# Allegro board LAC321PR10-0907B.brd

Outline 256.5 x 150.9 mm; copper layers: TOP, IN1, GND1, IN2, GND2, GND3, IN3, GND4, VCC, BOTTOM. Coordinates in mm from the lower left corner of the outline.
Outline path: 0,37.6 arc(0.15,37.95) 0.5,38.1 6.6,38.1 arc(8.8,40.3) 6.6,42.5 4.25,42.5 arc(3.9,42.65) 3.75,43 3.75,58.19 arc(3.6,58.54) 3.25,58.69 3.18,58.69 arc(2.83,58.84) 2.68,59.19 2.68,59.55 arc(2.53,59.9) 2.18,60.05 1.8,60.05 arc(1.45,60.2) 1.3,60.55 1.3,99.71 arc(1.45,100.06) 1.8,100.21 2.1,100.21 arc(2.45,100.36) 2.6,100.71 2.6,111.4 arc(2.75,111.75) 3.1,111.9 12.4,111.9 arc(12.75,111.75) 12.9,111.4 12.9,107.08 arc(12.83,106.83) 12.65,106.64 arc(12.54,105.86) 13.33,105.96 arc(13.51,106.14) 13.76,106.21 33.33,106.21 arc(33.58,106.14) 33.76,105.96 arc(34.55,105.86) 34.45,106.64 arc(34.26,106.83) 34.2,107.08 34.2,111.4 arc(34.34,111.75) 34.7,111.9 38.55,111.9 arc(38.9,112.05) 39.05,112.4 39.05,150.4 arc(39.2,150.75) 39.55,150.9 80.12,150.9 arc(80.47,150.75) 80.62,150.4 80.62,139.9 arc(80.77,139.55) 81.12,139.4 131.84,139.4 arc(132.19,139.25) 132.34,138.9 132.34,134.15 arc(132.49,133.8) 132.84,133.65 139,133.65 arc(139.35,133.8) 139.5,134.15 139.5,138.9 arc(139.65,139.25) 140,139.4 185.62,139.4 arc(185.97,139.55) 186.12,139.9 186.12,150.4 arc(186.27,150.75) 186.62,150.9 246,150.9 arc(246.35,150.75) 246.5,150.4 246.5,145.9 arc(246.65,145.55) 247,145.4 256,145.4 arc(256.35,145.25) 256.5,144.9 256.5,130.12 arc(256.35,129.77) 256,129.62 255.44,129.62 arc(255.09,129.48) 254.94,129.12 254.94,128.77 arc(254.79,128.42) 254.44,128.27 251.11,128.27 arc(250.86,128.34) 250.67,128.52 arc(249.89,128.63) 249.99,127.84 arc(250.17,127.66) 250.24,127.41 250.24,107.84 arc(250.17,107.59) 249.99,107.41 arc(249.89,106.62) 250.67,106.72 arc(250.86,106.91) 251.11,106.97 254.44,106.97 arc(254.79,106.83) 254.94,106.47 254.94,105 arc(254.79,104.65) 254.44,104.5 208.54,104.5 arc(208.21,104.38) 208.04,104.06 arc(207.88,103.75) 207.55,103.63 204.05,103.63 arc(203.8,103.69) 203.61,103.88 arc(202.83,103.98) 202.93,103.19 arc(203.11,103.01) 203.18,102.76 203.18,83.19 arc(203.11,82.94) 202.93,82.76 arc(202.83,81.97) 203.61,82.08 arc(203.8,82.26) 204.05,82.33 207.54,82.33 arc(207.89,82.18) 208.04,81.83 208.04,80.33 arc(207.89,79.98) 207.54,79.83 173.54,79.83 arc(173.19,79.98) 173.04,80.33 173.04,82.33 arc(172.89,82.68) 172.54,82.83 160.96,82.83 arc(160.63,82.95) 160.46,83.25 arc(159.61,84.74) 158,85.33 153,85.33 arc(151.39,84.74) 150.54,83.25 arc(150.36,82.95) 150.04,82.83 144.75,82.83 arc(144.4,82.68) 144.25,82.33 144.25,78.83 arc(144.1,78.48) 143.75,78.33 142.16,78.33 arc(141.84,78.45) 141.67,78.75 arc(139.1,80.93) 136.53,78.75 arc(136.36,78.45) 136.04,78.33 45.06,78.33 arc(44.02,78.62) 43.29,79.4 42.75,80.07 arc(39.35,79.63) 40.18,76.29 arc(40.96,75.56) 41.25,74.52 41.25,0.5 arc(41.1,0.15) 40.75,0 7,0 arc(6.65,0.15) 6.5,0.5 6.5,3.85 arc(6.62,4.17) 6.91,4.34 arc(8.69,6.7) 6.5,8.7 0.5,8.7 arc(0.15,8.85) 0,9.2 0,11.53 arc(0.15,11.88) 0.5,12.03 5,12.03 arc(5.5,11.53) 6,12.03 6,20.98 arc(5.5,21.48) 5,20.98 1.5,20.98 arc(1.15,21.13) 1,21.48 1,25.53 arc(1.15,25.88) 1.5,26.03 5,26.03 arc(5.5,25.53) 6,26.03 6,34.98 arc(5.5,35.48) 5,34.98 0.5,34.98 arc(0.15,35.13) 0,35.48 0,37.6

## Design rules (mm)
net group 8: nets H_PROCHOT# H_PROCHOT#_R
net group CLK_CK-XDP: nets CK_XDP CK_XDP#
net group CLK_PCIE2: nets CLK_PCIE2#_R CLK_PCIE2_R
net group CLK_PCIE3: nets CLK_PCIE3 CLK_PCIE3#
net group CLK_PCIE4: nets CLK_PCIE4 CLK_PCIE4#
net group CSI_SKYCAM-CSI0: nets SKYCAM_CSI0_D#_L SKYCAM_CSI0_D_L
net group CSI_SKYCAM-CSI2: nets SKYCAM_CSI2_D#_L SKYCAM_CSI2_D_L
net group CSI_SKYCAM-CSI3: nets SKYCAM_CSI3_D#_L SKYCAM_CSI3_D_L
net group CSI_SKYCAM-CSI-CLK-L: nets SKYCAM_USER_CSI_CLK_D#_L SKYCAM_USER_CSI_CLK_D_L
net group CSI_SYCAM-CSI1: nets SKYCAM_CSI1_D#_L SKYCAM_CSI1_D_L
net group CSI_SYCAM-USER-CSI0: nets SKYCAM_USER_CSI0_D#_L SKYCAM_USER_CSI0_D_L
net group CSI_SYCAM-USER-CSI1: nets SKYCAM_USER_CSI1_D#_L SKYCAM_USER_CSI1_D_L
net group DDI_BASE_DDI_AUX_DEV_D: nets BASE_DDI_AUX_DEV_DN BASE_DDI_AUX_DEV_DP
net group DDI_BASE_DDI_LANE0_DEV_D: nets BASE_DDI_LANE0_DEV_DN BASE_DDI_LANE0_DEV_DP
net group DDI_BASE_DDI_LANE1_DEV_D: nets BASE_DDI_LANE1_DEV_DN BASE_DDI_LANE1_DEV_DP
net group DDI_BASE_DDI_LANE2_DEV_D: nets BASE_DDI_LANE2_DEV_DN BASE_DDI_LANE2_DEV_DP
net group DDI_BASE_DDI_LANE3_DEV_D: nets BASE_DDI_LANE3_DEV_DN BASE_DDI_LANE3_DEV_DP
net group DIFFPAIR32: nets TBTA_CA2HD_0_N TBTA_CA2HD_0_P
net group DIFFPAIR33: nets TBTA_CA2HD_1_N TBTA_CA2HD_1_P
net group DIFFPAIR34: nets TBTB_CA2HD_0_N TBTB_CA2HD_0_P
net group DIFFPAIR35: nets TBTB_HD2CA_0_N TBTB_HD2CA_0_P
net group DIFFPAIR36: nets TBTB_TX0_N TBTB_TX0_P
net group DIFFPAIR37: nets TBTB_HD2CA_1_N TBTB_HD2CA_1_P
net group DIFFPAIR38: nets TBTB_CA2HD_1_N TBTB_CA2HD_1_P
net group DIFFPAIR39: nets TBTB_TX1_N TBTB_TX1_P
net group DIFFPAIR40: nets TBT_SNK0_ML0_N_L TBT_SNK0_ML0_P_L
net group DIFFPAIR41: nets TBT_SNK0_ML1_N_L TBT_SNK0_ML1_P_L
net group DIFFPAIR42: nets TBT_SNK0_ML2_N_L TBT_SNK0_ML2_P_L
net group DIFFPAIR43: nets TBT_SNK0_ML3_N_L TBT_SNK0_ML3_P_L
net group DIFFPAIR44: nets TBT_SNK0_AUX_N TBT_SNK0_AUX_P
net group DIFFPAIR45: nets TBT_SNK0_AUX_N_L TBT_SNK0_AUX_P_L
net group DIFFPAIR46: nets TBTB_USB2_D_N TBTB_USB2_D_P
net group DIFFPAIR47: nets TBTA_USB2_D_N TBTA_USB2_D_P
net group DIFFPAIR48: nets TBTB_AUX_N TBTB_AUX_P
net group DIFFPAIR49: nets TBTB_DPSRC_AUX_N TBTB_DPSRC_AUX_P
net group DIFFPAIR50: nets PCH_DDI1_AUXN PCH_DDI1_AUXP
net group DIFFPAIR51: nets TBT_SNK0_ML0_N TBT_SNK0_ML0_P
net group DIFFPAIR52: nets TBT_SNK0_ML1_N TBT_SNK0_ML1_P
net group DIFFPAIR53: nets TBT_SNK0_ML2_N TBT_SNK0_ML2_P
net group DIFFPAIR54: nets TBT_SNK0_ML3_N TBT_SNK0_ML3_P
net group DIFFPAIR56: nets USB3RN2 USB3RP2
net group DIFFPAIR57: nets USB3TN4 USB3TP4
net group DIFFPAIR59: nets USB3RN3 USB3RP3
net group DIFFPAIR60: nets USB3TN2_RC_CON USB3TP2_RC_CON
net group DIFFPAIR61: nets USB3RN2_RC_CON USB3RP2_RC_CON
net group DIFFPAIR67: nets CLK_PCIE4#_R CLK_PCIE4_R
net group DIFFPAIR68: nets CLK_PCIE3#_R CLK_PCIE3_R
net group DIFFPAIR69: nets SKYCAM_USER_CSI_CLK_D SKYCAM_USER_CSI_CLK_D#
net group DIFFPAIR70: nets USB3TN4_R USB3TP4_R
net group DIFFPAIR81: nets CLK_XDP#_L CLK_XDP_L
net group DIFFPAIR92: nets REM_DIODE3_N REM_DIODE3_P
net group DIFFPAIR93: nets REM_DIODE1_N REM_DIODE1_P
net group DP1_USB3TN3_RC_CON: nets USB3TN3_RC_CON USB3TP3_RC_CON
net group DP-PCH_DDI1_AUX: nets PCH_DDI1_AUXN_R PCH_DDI1_AUXP_R
net group DP_BASE_DDI_AUX_DEV_DN_L: nets BASE_DDI_AUX_DEV_DN_L BASE_DDI_AUX_DEV_DP_L
net group DP_BASE_DDI_LANE0_DEV_DN_L: nets BASE_DDI_LANE0_DEV_DN_L BASE_DDI_LANE0_DEV_DP_L
net group DP_BASE_DDI_LANE1_DEV_DN_L: nets BASE_DDI_LANE1_DEV_DN_L BASE_DDI_LANE1_DEV_DP_L
net group DP_BASE_DDI_LANE2_DEV_DN_L: nets BASE_DDI_LANE2_DEV_DN_L BASE_DDI_LANE2_DEV_DP_L
net group DP_BASE_DDI_LANE3_DEV_DN_L: nets BASE_DDI_LANE3_DEV_DN_L BASE_DDI_LANE3_DEV_DP_L
net group DP_CLK_PCIE2: nets CLK_PCIE2 CLK_PCIE2#
net group DP_PCH_DDI1_N0_R: nets PCH_DDI1_N0 PCH_DDI1_P0
net group DP_PCH_DDI1_N1_R: nets PCH_DDI1_N1 PCH_DDI1_P1
net group DP_PCH_DDI1_N2_R: nets PCH_DDI1_N2 PCH_DDI1_P2
net group DP_PCH_DDI1_N3_R: nets PCH_DDI1_N3 PCH_DDI1_P3
net group DP_SKYCAM_CSI0_D: nets SKYCAM_CSI0_D SKYCAM_CSI0_D#
net group DP_SKYCAM_CSI1_D: nets SKYCAM_CSI1_D SKYCAM_CSI1_D#
net group DP_SKYCAM_CSI2_D: nets SKYCAM_CSI2_D SKYCAM_CSI2_D#
net group DP_SKYCAM_CSI3_D: nets SKYCAM_CSI3_D SKYCAM_CSI3_D#
net group DP_SKYCAM_USER_CSI0_D: nets SKYCAM_USER_CSI0_D SKYCAM_USER_CSI0_D#
net group DP_SKYCAM_USER_CSI1_D: nets SKYCAM_USER_CSI1_D SKYCAM_USER_CSI1_D#
net group DP_USB3RN1_RC_CON: nets USB3RN1_RC_CON USB3RP1_RC_CON
net group DP_USB3TN2: nets USB3TN2 USB3TP2
net group DP_USB3TN3_RC_CON: nets N55977579 N55977609
net group DP_USB20_N5_R: nets USB20_N5_R USB20_P5_R
net group EDP_AUX-CON: nets EDP_AUXN_CONN EDP_AUXP_CONN
net group EDP_TX-P0-CON: nets EDP_TXN_P0_CONN EDP_TXP_P0_CONN
net group EDP_TX-P1-CON: nets EDP_TXN_P1_CONN EDP_TXP_P1_CONN
net group EDP_TX-P2-CON: nets EDP_TXN_P2_CONN EDP_TXP_P2_CONN
net group EDP_TX-P3-CON: nets EDP_TXN_P3_CONN EDP_TXP_P3_CONN
net group HP2_D: nets HP2_D_L HP2_D_R
net group HP2_D-C: nets HP2_D_L_C HP2_D_R_C
net group HP2_D-R: nets HP2_D_L_R HP2_D_R_R
net group LINE: nets LINE_L LINE_R
net group LINE1: nets LINE1_L LINE1_R
net group LINE1-C: nets LINE1_L_C LINE1_R_C
net group PCIE_PRX-DRX5-C: nets PCIE_PTX_DRX_N5_C PCIE_PTX_DRX_P5_C
net group PCIE_PRX-DRX7: nets PCIE_PTX_DRX_N7 PCIE_PTX_DRX_P7
net group PCIE_PRX-DRX7-C: nets PCIE_PTX_DRX_N7_C PCIE_PTX_DRX_P7_C
net group PCIE_PRX-DRX8: nets PCIE_PTX_DRX_N8 PCIE_PTX_DRX_P8
net group PCIE_PRX-DRX8-C: nets PCIE_PTX_DRX_N8_C PCIE_PTX_DRX_P8_C
net group PCIE_PRX-DRX9: nets PCIE_PTX_DRX_N9 PCIE_PTX_DRX_P9
net group PCIE_PRX-DRX9-C: nets PCIE_PTX_DRX_N9_C PCIE_PTX_DRX_P9_C
net group PCIE_PRX-DTX7: nets PCIE_PRX_DTX_N7 PCIE_PRX_DTX_P7
net group PCIE_PRX-DTX8: nets PCIE_PRX_DTX_N8 PCIE_PRX_DTX_P8
net group PCIE_PRX-DTX9: nets PCIE_PRX_DTX_N9 PCIE_PRX_DTX_P9
net group PCIE_PRX_DTX_7_R: nets PCIE_PRX_DTX_N7_R PCIE_PRX_DTX_P7_R
net group REM_DIODE2_N: nets REM_DIODE2_N REM_DIODE2_P
net group TBTA_I2C_D_N: nets TBTA_I2C_D_N TBTA_I2C_D_N_R
net group TBTA_I2C_D_P: nets TBTA_I2C_D_P TBTA_I2C_D_P_R
net group TBTA_USB2_D_N_R: nets TBTA_USB2_D_N_R USBC1_USB2_D_N_R
net group TBTA_USB2_D_P_R: nets TBTA_USB2_D_P_R USBC1_USB2_D_P_R
net group TBTB_I2C_D_N: nets TBTB_I2C_D_N TBTB_I2C_D_N_R
net group TBTB_I2C_D_P: nets TBTB_I2C_D_P TBTB_I2C_D_P_R
net group TBTB_USB2_D_N_R: nets TBTB_USB2_D_N_R USBC2_USB2_D_N_R
net group TBTB_USB2_D_P_R: nets TBTB_USB2_D_P_R USBC2_USB2_D_P_R
net group USB3_R1: nets USB3RN1 USB3RP1
net group USB3_R3: nets USB3RN3_RC_CON USB3RP3_RC_CON
net group USB3_R4: nets USB3RN4 USB3RP4
net group USB3_T2: nets USB3TN2_R USB3TP2_R
net group USB3_T3: nets USB3TN3 USB3TP3
net group USB20_5: nets USB20_N5 USB20_P5
net group USB20_N9: nets USB20_N9 USB20_N9_R
net group USB20_P9: nets USB20_P9 USB20_P9_R
net group 5: nets LPC_AD0 LPC_AD1 LPC_AD2 LPC_AD3 LPC_FRAME#
net group 43H: nets MEC_XTAL1 MEC_XTAL2 PBTN_OUT#_R
net group 45H: nets OSC_IN OSC_OUT PCH_RTCX1 PCH_RTCX2 XTAL24_IN XTAL24_OUT
net group CLK: nets CLK_PCIE5 CLK_PCIE5#_R CLK_PCIE5_R TBT_REFCLK_100_N TBT_REFCLK_100_N_R TBT_REFCLK_100_P TBT_REFCLK_100_P_R
net group CLK_PCIE5: nets CLK_PCIE5#
net group CSI: nets SKYCAM_CSI_CLK_D# SKYCAM_CSI_CLK_D#_L SKYCAM_CSI_CLK_D_L
net group DDI1: nets PCH_DDI1_N0_R PCH_DDI1_N1_R PCH_DDI1_N2_R PCH_DDI1_N3_R PCH_DDI1_P0_R PCH_DDI1_P1_R PCH_DDI1_P2_R PCH_DDI1_P3_R
net group DDI2: nets DPSNK1_AUX_N DPSNK1_AUX_P DPSNK1_ML0_N DPSNK1_ML0_P DPSNK1_ML1_N DPSNK1_ML1_P DPSNK1_ML2_N DPSNK1_ML2_P DPSNK1_ML3_N DPSNK1_ML3_P TBT_SNK1_AUX_N TBT_SNK1_AUX_P TBT_SNK1_ML0_N TBT_SNK1_ML0_P TBT_SNK1_ML1_N TBT_SNK1_ML1_P TBT_SNK1_ML2_N TBT_SNK1_ML2_P TBT_SNK1_ML3_N TBT_SNK1_ML3_P
net group DDR3_CKE: nets M_A_CKE0 M_A_CKE1 M_A_CKE2 M_A_CKE3 M_B_CKE0 M_B_CKE1 M_B_CKE2 M_B_CKE3
net group DDR3_M-A-CA0: nets M_A_CA_0_0 M_A_CA_0_1 M_A_CA_0_2 M_A_CA_0_3 M_A_CA_0_4 M_A_CA_0_5 M_A_CA_0_6 M_A_CA_0_7 M_A_CA_0_8 M_A_CA_0_9
net group DDR3_M-A-CA1: nets M_A_CA_1_0 M_A_CA_1_1 M_A_CA_1_2 M_A_CA_1_3 M_A_CA_1_4 M_A_CA_1_5 M_A_CA_1_6 M_A_CA_1_7 M_A_CA_1_8 M_A_CA_1_9
net group DDR3_M-B-CA0: nets M_B_CA_0_0 M_B_CA_0_1 M_B_CA_0_2 M_B_CA_0_3 M_B_CA_0_4 M_B_CA_0_5 M_B_CA_0_6 M_B_CA_0_7 M_B_CA_0_8 M_B_CA_0_9
net group DDR3_M-B-CA1: nets M_B_CA_1_0 M_B_CA_1_1 M_B_CA_1_2 M_B_CA_1_3 M_B_CA_1_4 M_B_CA_1_5 M_B_CA_1_6 M_B_CA_1_7 M_B_CA_1_8 M_B_CA_1_9
net group DDR_CTRL: nets M_A_CS0_N M_A_CS1_N M_A_ODT0 M_B_CS0_N M_B_CS1_N M_B_ODT0
net group DIFFPAIR58: nets SKYCAM_CSI_CLK_D
net group EDP_TX: nets EDP_AUXN EDP_AUXN_R EDP_AUXP EDP_AUXP_R EDP_TXN_P0 EDP_TXN_P0_R EDP_TXN_P1 EDP_TXN_P1_R EDP_TXN_P2 EDP_TXN_P2_R EDP_TXN_P3 EDP_TXN_P3_R EDP_TXP_P0 EDP_TXP_P0_R EDP_TXP_P1 EDP_TXP_P1_R EDP_TXP_P2 EDP_TXP_P2_R EDP_TXP_P3 EDP_TXP_P3_R
net group HDA: nets HDA_BIT_CLK_L HDA_RST#_L HDA_SDI0 HDA_SDIN0_AUDIO HDA_SDOUT HDA_SDOUT_L HDA_SYNC HDA_SYNC_L N126490934
net group I2C: nets GNSS_SCL
net group LPC: nets CLK_LPC_DEBUG CLK_PCI_MEC CLKOUT_LPC0 CLKOUT_LPC1
net group LPDDR3_DIFF: nets M_A_CK_DDR0_DN M_A_CK_DDR0_DP M_A_CK_DDR1_DN M_A_CK_DDR1_DP M_A_DQS_DN_0 M_A_DQS_DN_1 M_A_DQS_DN_2 M_A_DQS_DN_3 M_A_DQS_DN_4 M_A_DQS_DN_5 M_A_DQS_DN_6 M_A_DQS_DN_7 M_A_DQS_DP_0 M_A_DQS_DP_1 M_A_DQS_DP_2 M_A_DQS_DP_3 M_A_DQS_DP_4 M_A_DQS_DP_5 M_A_DQS_DP_6 M_A_DQS_DP_7 M_B_CK_DDR0_DN M_B_CK_DDR0_DP M_B_CK_DDR1_DN M_B_CK_DDR1_DP M_B_DQS_DN_0 M_B_DQS_DN_1 M_B_DQS_DN_2 M_B_DQS_DN_3 M_B_DQS_DN_4 M_B_DQS_DN_5 M_B_DQS_DN_6 M_B_DQS_DN_7 M_B_DQS_DP_0 M_B_DQS_DP_1 M_B_DQS_DP_2 M_B_DQS_DP_3 M_B_DQS_DP_4 M_B_DQS_DP_5 M_B_DQS_DP_6 M_B_DQS_DP_7
net group LPDDR3_SE: nets M_A_DQ_0 M_A_DQ_1 M_A_DQ_2 M_A_DQ_3 M_A_DQ_4 M_A_DQ_5 M_A_DQ_6 M_A_DQ_7 M_A_DQ_8 M_A_DQ_9 M_A_DQ_10 M_A_DQ_11 M_A_DQ_12 M_A_DQ_13 M_A_DQ_14 M_A_DQ_15 M_A_DQ_16 M_A_DQ_17 M_A_DQ_18 M_A_DQ_19 M_A_DQ_20 M_A_DQ_21 M_A_DQ_22 M_A_DQ_23 M_A_DQ_24 M_A_DQ_25 M_A_DQ_26 M_A_DQ_27 M_A_DQ_28 M_A_DQ_29 M_A_DQ_30 M_A_DQ_31 M_A_DQ_32 M_A_DQ_33 M_A_DQ_34 M_A_DQ_35 M_A_DQ_36 M_A_DQ_37 M_A_DQ_38 M_A_DQ_39 M_A_DQ_40 M_A_DQ_41 M_A_DQ_42 M_A_DQ_43 M_A_DQ_44 M_A_DQ_45 M_A_DQ_46 M_A_DQ_47 M_A_DQ_48 M_A_DQ_49 M_A_DQ_50 M_A_DQ_51 M_A_DQ_52 M_A_DQ_53 M_A_DQ_54 M_A_DQ_55 M_A_DQ_56 M_A_DQ_57 M_A_DQ_58 M_A_DQ_59 M_A_DQ_60 M_A_DQ_61 M_A_DQ_62 M_A_DQ_63 M_B_DQ_0 M_B_DQ_1 M_B_DQ_2 M_B_DQ_3 M_B_DQ_4 M_B_DQ_5 M_B_DQ_6 M_B_DQ_7 M_B_DQ_8 M_B_DQ_9 M_B_DQ_10 M_B_DQ_11 M_B_DQ_12 M_B_DQ_13 M_B_DQ_14 M_B_DQ_15 M_B_DQ_16 M_B_DQ_17 M_B_DQ_18 M_B_DQ_19 M_B_DQ_20 M_B_DQ_21 M_B_DQ_22 M_B_DQ_23 M_B_DQ_24 M_B_DQ_25 M_B_DQ_26 M_B_DQ_27 M_B_DQ_28 M_B_DQ_29 M_B_DQ_30 M_B_DQ_31 M_B_DQ_32 M_B_DQ_33 M_B_DQ_34 M_B_DQ_35 M_B_DQ_36 M_B_DQ_37 M_B_DQ_38 M_B_DQ_39 M_B_DQ_40 M_B_DQ_41 M_B_DQ_42 M_B_DQ_43 M_B_DQ_44 M_B_DQ_45 M_B_DQ_46 M_B_DQ_47 M_B_DQ_48 M_B_DQ_49 M_B_DQ_50 M_B_DQ_51 M_B_DQ_52 M_B_DQ_53 M_B_DQ_54 M_B_DQ_55 M_B_DQ_56 M_B_DQ_57 M_B_DQ_58 M_B_DQ_59 M_B_DQ_60 M_B_DQ_61 M_B_DQ_62 M_B_DQ_63
net group PCIE-ALPINE: nets PET0_N PET0_P PET1_N PET1_P PET2_N PET2_P PET3_N PET3_P TBT_PCIE_RX0_N TBT_PCIE_RX0_N_C TBT_PCIE_RX0_P TBT_PCIE_RX0_P_C TBT_PCIE_RX1_N TBT_PCIE_RX1_N_C TBT_PCIE_RX1_P TBT_PCIE_RX1_P_C TBT_PCIE_RX2_N TBT_PCIE_RX2_N_C TBT_PCIE_RX2_P TBT_PCIE_RX2_P_C TBT_PCIE_RX3_N TBT_PCIE_RX3_N_C TBT_PCIE_RX3_P TBT_PCIE_RX3_P_C TBT_PCIE_TX0_N TBT_PCIE_TX0_P TBT_PCIE_TX1_N TBT_PCIE_TX1_P TBT_PCIE_TX2_N TBT_PCIE_TX2_P TBT_PCIE_TX3_N TBT_PCIE_TX3_P
net group PCIE_WWAN: nets PCIE_PRX_DTX_N5 PCIE_PRX_DTX_N10 PCIE_PRX_DTX_N10_C PCIE_PRX_DTX_P5 PCIE_PRX_DTX_P10 PCIE_PRX_DTX_P10_C PCIE_PTX_DRX_N5 PCIE_PTX_DRX_N10 PCIE_PTX_DRX_N10_C PCIE_PTX_DRX_P5 PCIE_PTX_DRX_P10 PCIE_PTX_DRX_P10_C
net group S-CLK-15: nets CPU_XDP_TCK GNSS_SCL_L I2C0_SCL_AUD ISH_I2C1_SCL JTAG_CLK PCH_JTAG_TCK SKYCAM_I2C_CLK SMBCLK SML0CLK TS_I2C_SCL XDP_TCK1
net group SDIO: nets SD_CD# SD_CLK SD_CLK_L SD_CMD SD_CMD_L SD_D2 SD_D2_L SD_D3 SD_D3_L SD_RCLK_M SD_RCLK_M_L SD_RCLK_P SD_RCLK_P_L SP7_SDWP
net group SENSE-10-25: nets VCCGT_SENSE VCCSA_SENSE VCCSA_SENSE_1 VCCSENSE VCCSENSE_1 VSSGT_SENSE VSSGT_SENSE_1 VSSSA_SENSE VSSSA_SENSE_1 VSSSENSE VSSSENSE_1
net group SPACING-10: nets CFG0 CFG0_R CFG1 CFG2 CFG3 CFG4 CFG5 CFG6 CFG7 CFG8 CFG9 CFG10 CFG11 CFG12 CFG13 CFG14 CFG15 CFG16 CFG17 CFG18 CFG19 CPU_XDP_TDI CPU_XDP_TDO CPU_XDP_TMS GNSS_SDA GNSS_SDA_L I2C0_SDA_AUD ISH_I2C0_SCL ISH_I2C0_SDA ISH_I2C1_SDA JTAG_TDI JTAG_TDO JTAG_TMS N15739351 N15745290 N15745514 N16073129 N16073217 N16074745 N16074829 PCH_JTAG_TDO PCH_PLTRST# SIO_PWRBTN# SKYCAM_I2C_DATA SMBDATA SML0DATA SYS_PWROK SYS_PWROK_XDP TS_I2C_SDA TS_INT# TS_INT#_R XDP_BPM#0 XDP_BPM#1 XDP_BPM#2_R XDP_BPM#3_R XDP_OBS0 XDP_OBS1 XDP_PRSENT XDP_RST# XDP_TDI XDP_TDO XDP_TMS XDP_TRST#
net group SPACING-12: nets PCIE_RCOMPN PCIE_RCOMPP SOC_SVID_ALERT# SOC_SVID_ALERT#_R SOC_SVID_CLK SOC_SVID_CLK_R SOC_SVID_DAT SOC_SVID_DAT_R
net group SPACING-15: nets CPU_XDP_TRST# CSI2_COMP HDA_BIT_CLK HDA_RST# PLT_RST# RTC_RST# SDIO_RCOMP SSD_RST# SSD_RST#_Q SYS_RESET# TS_RST# WLAN_RST# WLAN_RST#_Q XDP_DBRESET#
net group SPACING-25: nets DDR_RCOMP_0 DDR_RCOMP_1 DDR_RCOMP_2
net group SPI: nets PCH_SPI_CLK PCH_SPI_CLK_R PCH_SPI_CS0# PCH_SPI_CS2# PCH_SPI_CS2#_R PCH_SPI_IO2 PCH_SPI_IO3 PCH_SPI_SCLK PCH_SPI_SI PCH_SPI_SI_MOSI PCH_SPI_SI_R PCH_SPI_SO PCH_SPI_SO_R SPI_CLK_ROM1 SPI_IO2_ROM1 SPI_IO3_ROM1 SPI_PCH_CLK SPI_PCH_CS0# SPI_PCH_IO2 SPI_PCH_IO3 SPI_PCH_SI SPI_PCH_SO SPI_SI_ROM1 SPI_SO_ROM1
net group USB: nets TBTA_AUX_N TBTA_AUX_P TBTA_DPSRC_AUX_N TBTA_DPSRC_AUX_P TBTA_HD2CA_0_N TBTA_HD2CA_0_P TBTA_HD2CA_1_N TBTA_HD2CA_1_P TBTA_TX0_N TBTA_TX0_P TBTA_TX1_N TBTA_TX1_P
net group USB20: nets USB20_N3 USB20_N3_R USB20_P3 USB20_P3_R
net group USB20_12_15(12): nets USB20_N1 USB20_N1_R USB20_P1 USB20_P1_R
net group USB30: nets USB3TN1 USB3TN1_R USB3TN1_RC_CON USB3TP1 USB3TP1_R USB3TP1_RC_CON USB20_N7 USB20_N7_CONN USB20_P7 USB20_P7_CONN
net group W10: nets +DVDDIO +IO_OUT +VDDQ_CPU_CLK BQ2477_CSIP BQ24777_CSIN BQ24777_CSON BQ24777_CSOP BQ24777_REGN DDR_VREF_CA I_BATT LINE1_VREFO N387666 N387808 N387812 N388012 N388144 N388398 N388550 N389038 N389071 N389075 N389103 N389365 N389486 N390129 N390245 N390884 N11072790 N14455165 N14455169 N14458758 N15733786 N15737096 N15739057 N15740039 N15740054 N15741283 N15743484 N15743562 N15743566 N15744978 N15744990 N15746436 N15749836 N15749896 N15750253 N15750329 N15773152 N16156133 N16313034 N16313116 N16454224 N16458110 N16458114 N16458329 N16458484 N16458488 N17426516 N17744387 N56067860 NTC_REF REG5 SABTS SAHGS SALGS SASWS SYSTHERM0 VCCGT_SENSE_1 VCCIO_SENSE VGATE VSSIO_SENSE
net group W12: nets CFG_RCOMP CPU_POPIRCOMP PCH_OPIRCOMP USB2_COMP
net group W20: nets +1.0V_APLL +1.0V_XDP +1.0VA_S +1.0VS_VCCIO_S +1.8V_MEM_S +1.8VA_S +3.3V_SPI +3VA_S +3VALW_EC_L +3VALW_S +3VS_AUDIO +3VS_TPM +3VS_TS +5VALW_S +EDP_COM +PBATT +RTCBATT +RTCVCC +SIM_PWR +V0.85A_S +V_DDR_0_DQ_VREF +V_DDR_1_DQ_VREF +V_DDR_VREF_CA +V_VDDQ_VTT BAT_B+ BOOT4 BOOT5 BOOT6 BOOT7 BOOT8 BOOT9 BOOT10 BOOT11 BOOT12 CPUDRVL1_1 CPUSW1 DV33_18 GTDRVL1_1 GTSW1 HG4 HG5 HG6 HG10 HG11 LG4 LG4-1 LG5 LG5-1 LG6 LG6-1 LG10 LG10-1 LG11-1 MOTOR_P1 N15991505 N125186177 P_AGND_1 SW4 SW5 SW6 SW7 SW8 SW9 SW10 TBTA_DC_SS TBTB_DC_SS VDDTAB3 VDDTAB4 WF_DVDD_1.2V
net group W40: nets CHG_LGATE CHG_SW CHG_UGATE
nets with their own width: min track width 0.254; nets TBTA_CC1 TBTA_CC2 TBTB_CC1 TBTB_CC2
nets with their own width: min track width 0.508; nets +1.0V_VCCSFR +1.0V_VCCST +1.0VS_VCCSTG +1.2V_VCCSFR_OC +1.2V_VDDQ +1.8V_MEM +1.8VS +1.8VS_AUDIO +3V_1.8V_HDA +3V_TBT +3VALW +3VS +5VALW +5VS +5VS_AUDIO +VCC_CORE +VCC_SA TBT_SVR_IND VCC0V9_CIO VCC0V9_DP VCC0V9_LVR_OUT VCC0V9_SVR VCC1V8D_TBTB_LDO VCC3V3_TBTA_LDO VCC3V3_TBTB_LDO VCC5V0_SYS
nets with their own width: min track width 0.61; nets +3VS_CR +VCCCOREG0 +VCCCOREG1
nets with their own width: min track width 1.016; nets +3VS_WLAN
nets with their own width: min track width 2.159; nets +1.0V_MPHYGT
nets with their own width: min track width 2.438; nets +1.0VS_VCCIO

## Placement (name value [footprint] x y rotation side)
C1  0.01U_0402_16V7K  [C_0402]  144.46 122.33 180 top
C2  .047U_0402_16V7K  [C_0402]  100.06 116.87 270 top
C3  .047U_0402_16V7K  [C_0402]  114.08 115.48 0 top
C4  .047U_0402_16V7K  [C_0402]  121.04 129.69 180 top
C5  .047U_0402_16V7K  [C_0402]  129.85 116.94 180 top
C6  0.022U_0402_16V7K~D  [C_0402]  106.15 125.33 270 top
C7  0.022U_0402_16V7K~D  [C_0402]  106.74 109.63 180 top
C8  0.022U_0402_16V7K~D  [C_0402]  119.92 128.38 270 top
C9  10U_0402_6.3V6M  [C_0402]  138.16 122.51 90 top
C10  10U_0402_6.3V6M  [C_0402]  123.27 127.68 90 top
C11  10U_0402_6.3V6M  [C_0402]  100.06 122.46 90 top
C12  10U_0402_6.3V6M  [C_0402]  114.15 121.12 90 top
C13  10U_0402_6.3V6M  [C_0402]  135.06 117.13 180 top
C14  10U_0402_6.3V6M  [C_0402]  138.16 127.11 270 top
C15  10U_0402_6.3V6M  [C_0402]  100.06 113.06 270 top
C16  10U_0402_6.3V6M  [C_0402]  123.17 119.03 270 top
C17  10U_0402_6.3V6M  [C_0402]  100.06 114.97 270 top
C18  10U_0402_6.3V6M  [C_0402]  138.16 124.29 90 top
C19  10U_0402_6.3V6M  [C_0402]  114.15 119.08 90 top
C20  10U_0402_6.3V6M  [C_0402]  114.15 113.62 90 top
C21  10U_0402_6.3V6M  [C_0402]  126.47 116.75 180 top
C22  10U_0402_6.3V6M  [C_0402]  123.32 129.55 180 top
C23  10U_0402_6.3V6M  [C_0402]  101.2 110.52 0 top
C24  10U_0402_6.3V6M  [C_0402]  105.01 110.52 0 top
C25  10U_0402_6.3V6M  [C_0402]  100.06 119.29 270 top
C26  10U_0402_6.3V6M  [C_0402]  103.78 124.96 0 top
C27  10U_0402_6.3V6M  [C_0402]  138.12 120.62 90 top
C28  10U_0402_6.3V6M  [C_0402]  123.17 119.97 90 top
C29  10U_0402_6.3V6M  [C_0402]  123.17 122 90 top
C30  10U_0402_6.3V6M  [C_0402]  103.1 110.52 0 top
C31  10U_0402_6.3V6M  [C_0402]  137.14 124.29 90 top
C32  10U_0402_6.3V6M  [C_0402]  122.52 126.3 180 top
C33  10U_0402_6.3V6M  [C_0402]  109.82 124.76 180 top
C34  10U_0402_6.3V6M  [C_0402]  124.39 117.13 180 top
C35  0.01U_0402_16V7K  [C_0402]  49.49 95.28 90 top
C36  0.01U_0402_16V7K  [C_0402]  57.51 95.72 90 top
C37  0.1U_0201_10V6K  [C_0201]  168 101.2 270 top
C38  0.1U_0201_10V6K  [C_0201]  173.97 99.56 90 top
C39  0.1U_0201_10V6K  [C_0201]  172.07 95.88 90 bottom
C40  0.1U_0201_10V6K  [C_0201]  172.7 95.88 90 bottom
C41  10U_0603_6.3V6M  [C_0603]  178.35 96.3 0 top
C42  0.1U_0201_10V6K  [C_0201]  173.59 95.88 90 bottom
C43  0.1U_0201_10V6K  [C_0201]  174.22 95.88 90 bottom
C44  0.1U_0201_10V6K  [C_0201]  174.99 95.88 90 bottom
C45  0.1U_0201_10V6K  [C_0201]  175.62 95.88 90 bottom
C46  0.1U_0201_10V6K  [C_0201]  176.93 95.66 180 top
C47  10U_0603_6.3V6M  [C_0603]  174.99 99.67 90 top
C48  33P_0402_50V8J  [C_0402]  177.35 96.43 180 top
C49  0.1U_0402_25V6  [C_0402]  184.52 102.08 270 top
C50  1U_0603_25V6K  [C_0603]  188.96 101.7 270 top
C51  10U_0402_6.3V6M  [C_0402]  101.06 129.45 270 top
C52  10U_0603_25V6M  [C_0603]  184.59 96.67 180 top
C53  0.1U_0201_10V6K  [C_0201]  242.27 130.04 0 top
C54  0.1U_0201_10V6K  [C_0201]  241.59 130.04 180 top
C55  0.1U_0201_10V6K  [C_0201]  238.49 130.35 90 top
C56  0.1U_0201_10V6K  [C_0201]  239.36 132.57 0 top
C57  2.2U_0402_6.3V6M  [C_0402]  51.29 95.72 90 top
C58  0.1U_0402_16V4Z  [C_0402]  185.53 95.97 90 top
C59  0.1U_0201_10V6K  [C_0201]  191.61 95.49 90 top
C65  22U_0603_6.3V6M  [C_0603]  244.39 108.63 90 top
C66  0.1U_0201_10V6K  [C_0201]  244.37 106.05 180 top
C67  15P_0402_50V8J  [C_0402]  244.53 106.79 180 top
C68  22U_0603_6.3V6M  [C_0603]  247.06 132.61 0 top
C69  0.1U_0201_10V6K  [C_0201]  246.81 130.7 0 top
C70  15P_0402_50V8J  [C_0402]  246.83 131.52 0 top
C71  0.1U_0201_10V6K  [C_0201]  37.73 105.06 0 top
C72  33P_0201_50V8J  [C_0201]  37.73 105.63 0 top
C73  22U_0603_6.3V6M  [C_0603]  11.49 99.78 90 top
C74  0.1U_0201_10V6K  [C_0201]  242.41 123.16 90 top
C75  22U_0603_6.3V6M  [C_0603]  36.62 105.82 90 top
C76  47P_0402_50V8J  [C_0402]  37.69 106.4 0 top
C77  0.1U_0201_10V6K  [C_0201]  13.32 100.11 90 top
C78  33P_0201_50V8J  [C_0201]  13.95 100.11 90 top
C79  47P_0402_50V8J  [C_0402]  12.55 99.98 90 top
C80  33P_0402_50V8J  [C_0402]  24.7 68.75 180 top
C81  1U_0402_6.3V6K  [C_0402]  24.7 69.64 180 top
C82  0.1U_0201_10V6K  [C_0201]  33.89 97.88 270 top
C83  33P_0402_50V8J  [C_0402]  24.62 74.15 90 top
C84  33P_0402_50V8J  [C_0402]  25.51 74.16 90 top
C85  33P_0402_50V8J  [C_0402]  25.75 69.64 270 top
C87  0.1U_0201_10V6K  [C_0201]  56.5 96.21 270 top
C88  0.1U_0201_10V6K  [C_0201]  55.86 96.21 270 top
C89  33P_0201_25V8F  [C_0201]  198.9 88.93 180 bottom
C90  4.7U_0603_6.3V6K  [C_0603]  205.92 107.75 270 top
C91  0.1U_0201_10V6K  [C_0201]  198.9 88.3 180 bottom
C92  0.01U_0201_16V7  [C_0201]  194.04 101.54 270 bottom
C93  47P_0402_50V8J  [C_0402]  204.84 107.2 270 top
C94  10U_0603_6.3V6M  [C_0603]  199.54 137.74 180 top
C95  0.1U_0201_10V6K  [C_0201]  200.3 137.43 90 top
C96  0.1U_0201_10V6K  [C_0201]  203.51 138.69 90 top
C97  0.1U_0201_10V6K  [C_0201]  202.94 138.69 90 top
C98  10U_0603_6.3V6M  [C_0603]  194.33 146.72 0 top
C99  4.7U_0402_6.3V6M  [C_0402]  194.6 145.58 0 top
C100  4.7U_0402_6.3V6M  [C_0402]  191.73 139.21 270 top
C101  0.1U_0201_10V6K  [C_0201]  194.23 143.67 0 bottom
C102  47P_0201_25V8J  [C_0201]  195.54 143.58 270 bottom
C103  0.1U_0201_10V6K  [C_0201]  194.23 142.15 0 bottom
C104  1U_0603_25V6K  [C_0603]  197.94 147.91 0 top
C105  1U_0603_25V6K  [C_0603]  188.63 140.37 90 top
C106  1U_0603_25V6K  [C_0603]  188.53 145.07 90 top
C107  1U_0402_6.3V6K  [C_0402]  193.81 139.54 270 top
C108  2.2U_0402_6.3V6M  [C_0402]  191.67 144.22 180 top
C109  0.1U_0201_10V6K  [C_0201]  55.23 96.21 270 top
C110  47U_0603_6.3V5  [C_0603]  190.93 148.5 180 top
C111  0.1U_0201_10V6K  [C_0201]  192.31 144.57 0 bottom
C112  0.1U_0201_10V6K  [C_0201]  48.16 93.63 270 top
C113  18P_0402_50V8J  [C_0402]  197.08 142.31 90 top
C114  18P_0402_50V8J  [C_0402]  197.59 139.67 270 top
C115  2200P_0402_50V7K  [C_0402]  196.15 139.56 270 top
C116  0.01UF_0402_25V7K  [C_0402]  197.25 137.68 180 top
C117  2200P_0402_50V7K  [C_0402]  194.7 138.63 90 top
C118  0.01UF_0402_25V7K  [C_0402]  194.6 137.7 0 top
C119  0.1U_0201_10V6K  [C_0201]  142.6 136.69 180 bottom
C120  0.1U_0201_10V6K  [C_0201]  146.16 137.19 180 bottom
C121  2.2U_0402_6.3V6M  [C_0402]  160.09 136.46 270 top
C122  0.1U_0201_10V6K  [C_0201]  148.57 137.19 0 bottom
C123  0.1U_0201_10V6K  [C_0201]  151.49 137.32 180 bottom
C124  0.1U_0201_10V6K  [C_0201]  142.6 136.08 180 bottom
C125  0.1U_0201_10V6K  [C_0201]  111.74 129.7 270 top
C126  2.2U_0402_6.3V6M  [C_0402]  83.69 129.24 180 top
C127  0.1U_0201_10V6K  [C_0201]  112.38 129.74 270 top
C128  0.1U_0201_10V6K  [C_0201]  53.57 86.3 270 top
C129  0.1U_0201_10V6K  [C_0201]  100.32 129.51 270 top
C130  0.1U_0201_10V6K  [C_0201]  99.74 129.51 270 top
C131  0.1U_0201_10V6K  [C_0201]  117.14 123.19 90 top
C132  0.1U_0201_10V6K  [C_0201]  117.77 123.19 90 top
C133  0.1U_0201_10V6K  [C_0201]  47.53 93.63 270 top
C134  0.1U_0201_10V6K  [C_0201]  54.21 86.3 270 top
C135  0.1U_0201_10V6K  [C_0201]  203.97 131.3 180 top
C136  0.1U_0201_10V6K  [C_0201]  52.94 86.3 270 top
C137  0.1U_0201_10V6K  [C_0201]  18.27 96.26 90 top
C138  0.1U_0201_10V6K  [C_0201]  32.1 83.88 270 top
C139  10U_0402_6.3V6M  [C_0402]  218.27 111.15 180 top
C140  0.1U_0201_10V6K  [C_0201]  217.99 108.91 180 top
C141  0.1U_0201_10V6K  [C_0201]  31.46 83.88 270 top
C142  0.1U_0201_10V6K  [C_0201]  54.59 96.21 270 top
C143  0.1U_0201_10V6K  [C_0201]  53.96 96.21 270 top
C144  0.1U_0201_10V6K  [C_0201]  53.32 96.21 270 top
C145  0.1U_0201_10V6K  [C_0201]  52.69 96.21 270 top
C146  0.1U_0201_10V6K  [C_0201]  52.05 96.21 270 top
C147  0.1U_0201_10V6K  [C_0201]  52.3 86.3 270 top
C148  1U_0603_25V6K  [C_0603]  188.53 142.72 90 top
C149  2.2U_0402_6.3V6M  [C_0402]  109.82 129.65 270 top
C150  0.22U_0201_6.3V6M  [C_0201]  65.39 147.68 180 top
C151  100P_0201_50V8J  [C_0201]  65.39 148.28 180 top
C152  0.1U_0201_10V6K  [C_0201]  51.67 86.3 270 top
C153  1U_0603_25V6K  [C_0603]  110.85 129.57 270 top
C154  0.1U_0201_10V6K  [C_0201]  51.03 86.3 270 top
C155  0.1U_0201_10V6K  [C_0201]  49.51 86.3 270 top
C156  0.1U_0201_10V6K  [C_0201]  218.32 110.4 180 top
C157  0.1U_0201_10V6K  [C_0201]  82.53 134.63 90 top
C158  0.1U_0201_10V6K  [C_0201]  18.9 96.26 90 top
C159  0.1U_0201_10V6K  [C_0201]  49.73 89.57 0 bottom
C160  0.1U_0201_10V6K  [C_0201]  60.78 88.76 0 top
C161  0.1U_0201_10V6K  [C_0201]  80.12 133.93 270 top
C162  10P_0402_50V8J  [C_0402]  81.53 133.89 0 top
C165  0.1U_0201_10V6K  [C_0201]  109.19 128.04 0 top
C169  39P_0201_50V8J  [C_0201]  189.97 136.6 270 top
C170  39P_0201_50V8J  [C_0201]  190.73 136.6 270 top
C171  0.1U_0402_10V7K  [C_0402]  15.14 99.42 270 top
C176  0.1U_0201_10V6K  [C_0201]  232.24 125.78 90 bottom
C177  0.1U_0201_10V6K  [C_0201]  230.49 128.39 90 top
C178  0.1U_0201_10V6K  [C_0201]  228.43 125.36 90 top
C179  10U_0603_6.3V6M  [C_0603]  224.77 125.19 270 top
C180  0.1U_0201_10V6K  [C_0201]  230.74 121.06 180 bottom
C181  0.1U_0201_10V6K  [C_0201]  230.36 125.76 90 bottom
C182  0.1U_0201_10V6K  [C_0201]  230.97 125.73 90 bottom
C183  0.1U_0201_10V6K  [C_0201]  233.66 120.18 0 bottom
C184  0.1U_0201_10V6K  [C_0201]  233.41 125.76 90 bottom
C185  0.1U_0201_10V6K  [C_0201]  237.79 124.67 0 top
C186  0.1U_0201_10V6K  [C_0201]  231.6 125.73 90 bottom
C187  0.1U_0201_10V6K  [C_0201]  235.25 121.75 0 bottom
C188  0.1U_0201_10V6K  [C_0201]  235.31 126.29 270 bottom
C189  4700P_0402_25V7K  [C_0402]  232.62 128.41 90 top
C190  1U_0402_6.3V6K  [C_0402]  235.95 130.26 90 top
C191  2200P_0402_50V7K  [C_0402]  233.15 118.78 0 top
C192  2200P_0402_50V7K  [C_0402]  235.9 118.91 180 top
C193  2200P_0402_50V7K  [C_0402]  236.76 118.91 0 top
C194  15P_0402_50V8J  [C_0402]  237.83 127.29 270 top
C195  18P_0402_50V8J  [C_0402]  237.83 128.15 90 top
C196  4.7U_0603_6.3V6K  [C_0603]  231.5 128.37 90 top
C197  1U_0402_6.3V4Z  [C_0402]  238.86 119.63 270 top
C198  4.7P_0402_50V8C  [C_0402]  227.21 122.77 0 top
C199  0.1U_0402_10V7K  [C_0402]  234.68 117.58 270 top
C200  0.1U_0402_10V7K  [C_0402]  195.23 106.59 0 top
C202  0.1U_0201_10V6K  [C_0201]  48.88 86.3 270 top
C203  0.1U_0201_10V6K  [C_0201]  227.7 125.94 180 top
C204  100P_0402_50V8J  [C_0402]  112.6 126.47 270 top
C205  0.1U_0201_10V6K  [C_0201]  227.7 127.71 180 top
C206  0.1U_0201_10V6K  [C_0201]  59.54 86.3 270 top
C207  100P_0201_50V8J  [C_0201]  189.85 139.06 90 top
C208  100P_0402_50V8J  [C_0402]  94.47 123.94 90 top
C209  100P_0402_50V8J  [C_0402]  223.22 116.66 0 top
C210  0.1U_0201_10V6K  [C_0201]  195.56 131.73 90 top
C211  1U_0402_6.3V6K  [C_0402]  233.46 135.49 180 top
C212  1U_0402_6.3V6K  [C_0402]  141.38 124.11 0 top
C213  1000P_0402_25V8J  [C_0402]  143 126.03 0 top
C214  2200P_0402_25V7K  [C_0402]  237.97 135.22 0 top
C215  1U_0402_6.3V6K  [C_0402]  241.57 132.67 180 top
C216  0.1U_0201_10V6K  [C_0201]  193.66 127.83 270 top
C217  2200P_0402_25V7K  [C_0402]  194.42 132.62 90 top
C218  0.1U_0201_10V6K  [C_0201]  192.26 133.55 270 top
C219  0.1U_0201_10V6K  [C_0201]  233.52 137.47 180 top
C220  100P_0402_50V8J  [C_0402]  19.11 19.85 180 top
C221  100P_0402_50V8J  [C_0402]  38.6 107.29 180 top
C222  0.1U_0201_10V6K  [C_0201]  33 95.69 90 top
C223  0.1U_0201_10V6K  [C_0201]  238.77 138.11 180 top
C224  2200P_0402_25V7K  [C_0402]  237.97 136.11 0 top
C225  4700P_0402_16V7K  [C_0402]  197.34 124.19 270 top
C227  1000P_0402_25V8J  [C_0402]  100.54 84.2 270 top
C228  22P_0402_50V8J  [C_0402]  123.9 89.4 270 top
C229  0.1U_0201_10V6K  [C_0201]  98.66 87.96 270 top
C230  1U_0402_6.3V6K  [C_0402]  100.51 82.4 0 top
C231  0.1U_0201_10V6K  [C_0201]  35.79 96.05 0 top
C232  0.1U_0201_10V6K  [C_0201]  197.17 128.81 0 top
C233  0.1U_0201_10V6K  [C_0201]  187.94 106.5 270 top
C234  4700P_0402_16V7K  [C_0402]  38.39 85.25 0 top
C235  0.1U_0201_10V6K  [C_0201]  193.66 101.85 90 top
C236  2200P_0402_25V7K  [C_0402]  191.24 105.75 90 top
C237  2200P_0402_25V7K  [C_0402]  192.13 105.75 90 top
C238  0.1U_0201_10V6K  [C_0201]  194.16 106.5 270 top
C239  2200P_0402_25V7K  [C_0402]  101.43 84.2 270 top
C240  0.1U_0201_10V6K  [C_0201]  190.52 100.62 180 top
C241  0.1U_0402_10V7K  [C_0402]  102.19 89 90 top
C242  0.1U_0402_10V7K  [C_0402]  103.64 83.34 90 top
C243  0.1U_0201_10V6K  [C_0201]  24.09 67.99 0 top
C244  1000P_0402_25V8J  [C_0402]  28.3 66.4 0 top
C245  220P_0402_50V8K  [C_0402]  28.3 65.51 0 top
C246  0.1U_0201_10V6K  [C_0201]  23.09 64.3 180 top
C247  2200P_0402_25V7K  [C_0402]  34.78 90.87 270 top
C248  0.1U_0201_10V6K  [C_0201]  35.92 88.67 270 top
C249  1U_0402_6.3V6K  [C_0402]  152.83 96.79 0 top
C250  0.1U_0201_10V6K  [C_0201]  32.84 88.43 0 top
C251  22P_0402_50V8J  [C_0402]  123.01 89.4 270 top
C252  0.1U_0201_10V6K  [C_0201]  196.49 128.81 180 top
C253  0.1U_0201_10V6K  [C_0201]  34.94 87.54 180 top
C254  100P_0201_50V8J  [C_0201]  190.73 139.06 90 top
C255  1U_0402_6.3V6K  [C_0402]  150.81 92.67 90 top
C256  0.1U_0201_10V6K  [C_0201]  139.59 129.81 180 top
C257  0.1U_0201_10V6K  [C_0201]  142.54 125.27 0 top
C258  0.1U_0201_10V6K  [C_0201]  60.18 86.3 270 top
C259  0.1U_0201_10V6K  [C_0201]  58.91 86.3 270 top
C260  0.1U_0201_10V6K  [C_0201]  58.27 86.3 270 top
C261  0.1U_0201_10V6K  [C_0201]  140.66 128.66 0 top
C262  0.1U_0201_10V6K  [C_0201]  57.64 86.3 270 top
C263  2200P_0402_25V7K  [C_0402]  145.69 126.04 180 top
C264  0.1U_0201_10V6K  [C_0201]  57 86.3 270 top
C265  0.1U_0201_10V6K  [C_0201]  55.48 86.3 270 top
C266  0.1U_0201_10V6K  [C_0201]  54.84 86.3 270 top
C267  0.1U_0201_10V6K  [C_0201]  229.09 128.39 90 top
C268  22P_0402_50V8J  [C_0402]  125.58 92.68 90 top
C269  22P_0402_50V8J  [C_0402]  124.69 92.68 90 top
C273  220P_0402_50V8K  [C_0402]  196.45 124.19 270 top
C274  0.1U_0201_10V6K  [C_0201]  197.25 122.46 180 top
C275  0.1U_0201_10V6K  [C_0201]  195.69 121.86 270 top
C276  0.1U_0201_10V6K  [C_0201]  40.11 85.54 270 top
C277  0.1U_0201_10V6K  [C_0201]  29.23 68.44 180 top
C278  0.1U_0201_10V6K  [C_0201]  29.23 69.07 180 top
C279  22P_0201_50V8J  [C_0201]  95.62 129.32 180 top
C280  22P_0201_50V8J  [C_0201]  95.62 128.43 180 top
C283  22P_0201_50V8J  [C_0201]  95.69 127.54 180 top
C284  22P_0201_50V8J  [C_0201]  95.69 125.89 180 top
C288  220P_0402_50V8K  [C_0402]  14.75 48.25 0 top
C289  220P_0402_50V8K  [C_0402]  13.01 48.24 0 top
C290  220P_0402_50V8K  [C_0402]  29.37 48.73 0 top
C291  220P_0402_50V8K  [C_0402]  29.37 47.84 0 top
C377  10U_0402_6.3V6M  [C_0402]  31.48 89.54 90 top
C410  0.1U_0201_10V6K  [C_0201]  169.08 95.88 90 bottom
C411  0.1U_0201_10V6K  [C_0201]  169.72 95.88 90 bottom
C412  0.1U_0201_10V6K  [C_0201]  170.54 95.88 90 bottom
C413  0.1U_0201_10V6K  [C_0201]  171.24 95.88 90 bottom
C415  15P_0402_50V8J  [C_0402]  163.91 95.59 90 top
C715  1U_0402_6.3V6K  [C_0402]  227.56 143.1 180 top
C1164  0.1U_0201_10V6K  [C_0201]  221.61 123.46 0 top
C1222  0.1U_0201_10V6K  [C_0201]  164.23 92.49 180 bottom
C1223  0.1U_0201_10V6K  [C_0201]  187.31 105.15 90 top
C1224  0.1U_0402_25V7K  [C_0402]  185.41 101.25 90 top
C1227  0.1U_0201_10V6K  [C_0201]  156.7 95.03 0 top
C1228  1U_0402_6.3V6K  [C_0402]  156.75 93.12 0 top
C1229  0.1U_0201_10V6K  [C_0201]  151.54 93.05 90 top
C1230  1000P_0402_50V7K  [C_0402]  152.06 94.42 180 top
C1231  1000P_0402_50V7K  [C_0402]  152.06 95.31 180 top
C1232  0.1U_0201_10V6K  [C_0201]  151.95 96.05 180 top
C1233  1U_0402_6.3V6K  [C_0402]  156.75 95.79 0 top
C1234  0.1U_0201_10V6K  [C_0201]  99.93 94.61 90 top
C1235  0.1U_0201_10V6K  [C_0201]  105.57 92.91 90 top
C1236  0.1U_0201_10V6K  [C_0201]  141.85 86.03 90 top
C1237  0.1U_0201_10V6K  [C_0201]  134.95 87.38 270 top
C1238  2200P_0402_25V7K  [C_0402]  33.89 90.87 270 top
C1242  0.1U_0201_10V6K  [C_0201]  104.47 83.02 270 top
C1243  0.1U_0201_10V6K  [C_0201]  105.11 83.02 270 top
C1244  0.1U_0201_10V6K  [C_0201]  11.47 94.06 0 top
C1245  0.1U_0201_10V6K  [C_0201]  13.35 94.06 180 top
C1246  100P_0402_50V8J  [C_0402]  83.12 128.39 270 top
C1248  6800P_0402_25V7K  [C_0402]  242.93 131.86 270 top
C1249  0.01U_0402_25V7K  [C_0402]  218.26 112.05 180 top
C1250  0.1U_0402_25V6  [C_0402]  218.26 109.65 180 top
C1251  0.22U_0201_6.3V6M  [C_0201]  27.03 43.25 270 top
C1252  0.22U_0201_6.3V6M  [C_0201]  26.46 43.29 270 top
C1253  0.22U_0201_6.3V6M  [C_0201]  23.65 43.26 270 top
C1254  0.22U_0201_6.3V6M  [C_0201]  28 43.25 270 top
C1255  0.22U_0201_6.3V6M  [C_0201]  28.81 43.25 270 top
C1256  0.22U_0201_6.3V6M  [C_0201]  24.36 43.25 270 top
C1257  0.22U_0201_6.3V6M  [C_0201]  25 43.25 270 top
C1258  0.22U_0201_6.3V6M  [C_0201]  23.02 43.26 270 top
C1259  20P_0402_50V8  [C_0402]  21.03 42.45 0 top
C1260  20P_0402_50V8  [C_0402]  20.17 42.45 180 top
C1261  0.1U_0201_6.3V6K  [C_0201]  32.04 37.57 0 top
C1262  0.1U_0201_6.3V6K  [C_0201]  32.04 38.15 0 top
C1263  0.1U_0201_6.3V6K  [C_0201]  32.04 39.29 0 top
C1264  0.1U_0201_6.3V6K  [C_0201]  32.02 38.72 0 top
C1265  0.1U_0201_6.3V6K  [C_0201]  32.04 40.43 0 top
C1266  0.1U_0201_6.3V6K  [C_0201]  32.04 39.86 0 top
C1267  0.1U_0201_6.3V6K  [C_0201]  32.04 41.58 0 top
C1268  0.1U_0201_6.3V6K  [C_0201]  32.04 41 0 top
C1269  0.1U_0201_6.3V6K  [C_0201]  32.05 36.43 0 top
C1270  0.1U_0201_6.3V6K  [C_0201]  32.05 37 0 top
C1271  0.1U_0201_6.3V6K  [C_0201]  33.69 38.09 0 top
C1272  0.22U_0201_6.3V6M  [C_0201]  14.94 36.39 45 bottom
C1273  0.22U_0201_6.3V6M  [C_0201]  17.75 32.56 0 top
C1274  0.22U_0201_6.3V6M  [C_0201]  14.53 36.8 45 bottom
C1275  0.22U_0201_6.3V6M  [C_0201]  17.75 33.14 0 top
C1276  0.22U_0201_6.3V6M  [C_0201]  16.61 38.73 0 bottom
C1277  0.22U_0201_6.3V6M  [C_0201]  17.84 34.58 0 top
C1278  0.22U_0201_6.3V6M  [C_0201]  16.61 38.1 0 bottom
C1279  0.22U_0201_6.3V6M  [C_0201]  17.85 34.01 0 top
C1280  0.1U_0201_6.3V6K  [C_0201]  30.85 37.59 180 bottom
C1281  0.1U_0201_6.3V6K  [C_0201]  30.87 38.3 180 bottom
C1282  0.1U_0201_6.3V6K  [C_0201]  30.85 37.02 180 bottom
C1283  0.1U_0201_6.3V6K  [C_0201]  30.87 38.87 180 bottom
C1284  1U_0201_6.3V6M  [C_0201]  22.1 32.46 180 bottom
C1285  1U_0201_6.3V6M  [C_0201]  34.28 38.67 180 top
C1286  1U_0201_6.3V6M  [C_0201]  26.21 36.27 270 bottom
C1287  1U_0201_6.3V6M  [C_0201]  21.91 33.69 0 bottom
C1288  10U_0402_6.3V6M  [C_0402]  17.2 30.22 270 top
C1289  10U_0402_6.3V6M  [C_0402]  16.27 32.01 180 top
C1290  10U_0402_6.3V6M  [C_0402]  16.27 31.12 180 top
C1291  10U_0402_6.3V6M  [C_0402]  16.33 30.22 270 top
C1292  1U_0201_6.3V6M  [C_0201]  23.82 33.75 0 bottom
C1293  1U_0201_6.3V6M  [C_0201]  25.61 33.75 180 bottom
C1294  1U_0201_6.3V6M  [C_0201]  24.33 40.06 0 bottom
C1295  1U_0201_6.3V6M  [C_0201]  25.55 35.59 180 bottom
C1296  1U_0201_6.3V6M  [C_0201]  26.06 34.35 180 bottom
C1297  1U_0201_6.3V6M  [C_0201]  30.19 35.34 180 bottom
C1298  1U_0201_6.3V6M  [C_0201]  30.19 35.91 180 bottom
C1299  1U_0201_6.3V6M  [C_0201]  25.47 32.37 0 bottom
C1300  1U_0201_6.3V6M  [C_0201]  21 36.27 270 bottom
C1301  1U_0201_6.3V6M  [C_0201]  20.59 33.9 90 bottom
C1302  1U_0201_6.3V6M  [C_0201]  21.16 33.9 90 bottom
C1303  1U_0201_6.3V6M  [C_0201]  19.86 36.27 270 bottom
C1304  1U_0201_6.3V6M  [C_0201]  20.43 36.27 270 bottom
C1305  1U_0201_6.3V6M  [C_0201]  20.02 33.9 90 bottom
C1306  1U_0201_6.3V6M  [C_0201]  23.03 36.5 270 bottom
C1307  1U_0201_6.3V6M  [C_0201]  26.37 40.1 180 bottom
C1308  1U_0201_6.3V6M  [C_0201]  26.37 40.67 180 bottom
C1309  1U_0201_6.3V6M  [C_0201]  24.33 40.64 0 bottom
C1315  1U_0201_6.3V6M  [C_0201]  25.66 36.86 0 bottom
C1319  10U_0402_6.3V6M  [C_0402]  24.25 45.33 90 top
C1320  10U_0402_6.3V6M  [C_0402]  23.37 45.33 90 top
C1323  1U_0201_6.3V6M  [C_0201]  27.45 34.26 180 bottom
C1324  1U_0201_6.3V6M  [C_0201]  28.09 32.99 180 bottom
C1325  1U_0201_6.3V6M  [C_0201]  26.78 35.63 270 bottom
C1326  1U_0201_6.3V6M  [C_0201]  23.7 38.39 180 bottom
C1327  1U_0201_6.3V6M  [C_0201]  23.16 37.09 0 bottom
C1328  2.2U_0402_6.3V6M  [C_0402]  7.83 53.6 180 top
C1329  1U_0201_6.3V6K  [C_0201]  10.05 52.12 180 bottom
C1330  10U_0402_6.3V6M  [C_0402]  7.83 51.65 180 top
C1331  22U_0603_6.3V6M  [C_0603]  14 56.61 90 top
C1332  22U_0603_6.3V6M  [C_0603]  19.09 57.56 0 top
C1333  22U_0603_6.3V6M  [C_0603]  17.32 55.57 270 top
C1334  22U_0603_6.3V6M  [C_0603]  16.11 55.57 270 top
C1335  2.2U_0402_6.3V6M  [C_0402]  7.77 47.06 180 top
C1336  2.2U_0402_6.3V6M  [C_0402]  10.17 56.31 90 top
C1337  1U_0603_25V6  [C_0603]  18.77 48.42 180 top
C1338  10U_0603_25V6M  [C_0603]  7.85 50.6 180 top
C1339  1U_0603_25V6  [C_0603]  15.97 51.31 0 top
C1340  4.7U_0603_25V6K  [C_0603]  11.25 57.74 270 top
C1341  4.7U_0603_25V6K  [C_0603]  28.98 56.94 90 top
C1342  0.1U_0201_10V6K  [C_0201]  17.65 41.68 270 bottom
C1343  0.22U_0402_16V7K  [C_0402]  16.02 52.37 0 top
C1344  2.2U_0402_6.3V6M  [C_0402]  21.57 56.47 90 top
C1345  1U_0201_6.3V6K  [C_0201]  23.34 50.53 180 bottom
C1346  10U_0402_6.3V6M  [C_0402]  21.13 50.19 180 top
C1347  22U_0603_6.3V6M  [C_0603]  31.43 56.93 90 top
C1348  22U_0603_6.3V6M  [C_0603]  30.21 56.93 90 top
C1349  22U_0603_6.3V6M  [C_0603]  33.88 56.92 90 top
C1350  22U_0603_6.3V6M  [C_0603]  32.65 56.93 90 top
C1351  2.2U_0402_6.3V6M  [C_0402]  20.09 47.35 270 top
C1352  2.2U_0402_6.3V6M  [C_0402]  22.9 56.02 90 top
C1353  1U_0603_25V6  [C_0603]  32.25 45.51 0 top
C1354  10U_0603_25V6M  [C_0603]  21.13 49.02 180 top
C1355  1U_0603_25V6  [C_0603]  29.58 51.06 0 top
C1358  0.22U_0402_16V7K  [C_0402]  31.71 44.47 0 top
C1359  0.47U_0201_25V  [C_0201]  9.43 31.22 180 bottom
C1360  0.47U_0201_25V  [C_0201]  9.23 17.72 180 bottom
C1361  0.47U_0201_25V  [C_0201]  9.23 17.15 180 bottom
C1362  0.47U_0201_25V  [C_0201]  10.33 26.25 90 top
C1363  0.47U_0201_25V  [C_0201]  10.79 20.28 270 top
C1364  0.47U_0201_25V  [C_0201]  10.56 12.25 90 top
C1365  0.47U_0201_25V  [C_0201]  9.43 31.8 180 bottom
C1366  0.47U_0201_25V  [C_0201]  10.85 35.39 270 top
C1384  100U_A_6.3VM_R70M  [C_A]  9.76 100.36 90 top
C1385  100U_A_6.3VM_R70M  [C_A]  12.96 98.43 270 top
C1386  1U_0201_6.3V6K  [C_0201]  219.56 123.46 180 top
C1387  10U_0603_6.3V6M  [C_0603]  203.35 137.78 180 top
C1388  0.1U_0201_10V6K  [C_0201]  94.86 98.64 180 top
C1389  2200P_0402_25V7K  [C_0402]  91.67 98.46 180 top
C1390  0.1U_0201_10V6K  [C_0201]  93.72 101.91 0 top
C1391  100P_0201_50V8J  [C_0201]  65.39 147.09 180 top
C1392  100P_0201_50V8J  [C_0201]  66.71 147.7 180 top
C1393  100P_0201_50V8J  [C_0201]  66.72 146.55 180 top
C1394  100P_0201_50V8J  [C_0201]  66.72 145.37 270 top
C1395  0.1U_0402_10V7K  [C_0402]  47.57 88.03 270 top
C1396  0.1U_0402_10V7K  [C_0402]  48.46 88.03 270 top
C1397  100P_0201_50V8J  [C_0201]  28.04 26.73 180 top
C1398  100P_0201_50V8J  [C_0201]  101.95 129.56 270 top
C1399  100P_0201_50V8J  [C_0201]  114.64 129.66 270 top
C1400  100P_0201_50V8J  [C_0201]  115.27 129.66 270 top
C1401  47U_0603_6.3V  [C_0603]  17.7 22.42 180 top
C1402  47U_0603_6.3V  [C_0603]  17.7 21.2 180 top
C1403  47U_0603_6.3V  [C_0603]  16.3 23.64 0 top
C1404  47U_0603_6.3V  [C_0603]  15.06 22.98 270 top
C1405  47U_0603_6.3V  [C_0603]  14.98 24.06 180 top
C1406  1U_0201_6.3V6M  [C_0201]  20.42 40.41 0 bottom
C1407  1U_0201_6.3V6M  [C_0201]  20.42 39.68 0 bottom
C1408  47P_0201_25V8J  [C_0201]  202.9 147.16 90 top
C1409  47P_0201_25V8J  [C_0201]  93.11 129.37 180 top
C1410  47P_0201_25V8J  [C_0201]  113.86 129.34 270 top
C1411  47P_0201_25V8J  [C_0201]  198.29 146.58 180 top
C1412  47P_0201_25V8J  [C_0201]  189.63 141.47 270 top
C1413  47P_0201_25V8J  [C_0201]  190.06 144.66 180 top
C1414  47P_0201_25V8J  [C_0201]  109.77 127.47 180 top
C1415  47P_0201_25V8J  [C_0201]  189.41 142.55 90 top
C1416  47P_0201_25V8J  [C_0201]  189.14 147.61 0 top
C1417  47P_0201_25V8J  [C_0201]  190.37 147.01 270 top
C1418  47P_0201_25V8J  [C_0201]  189.74 147.02 270 top
C1419  2.2U_0402_25V6M  [C_0402]  114.66 87.47 90 top
C1420  2.2U_0402_25V6M  [C_0402]  100.51 80.55 90 top
C1421  0.1U_0402_25V6  [C_0402]  115.54 87.47 90 top
C1422  0.1U_0402_25V6  [C_0402]  101.42 80.55 90 top
C1423  0.1U_0402_25V6  [C_0402]  14.27 37.16 90 top
C1424  0.1U_0402_25V6  [C_0402]  13.89 19.74 0 top
C1425  100P_0201_50V8J  [C_0201]  230.63 142.53 0 top
C1426  100P_0201_50V8J  [C_0201]  247.55 140.03 270 top
C1427  100P_0201_50V8J  [C_0201]  247.69 141.12 0 top
C1428  100P_0201_50V8J  [C_0201]  249.47 141.12 180 top
C1429  47P_0201_25V8J  [C_0201]  157.6 137.07 180 top
C1430  47P_0201_25V8J  [C_0201]  203.63 148.51 270 top
C1431  22U_0603_6.3V6M  [C_0603]  150.97 136.39 270 top
C1432  22U_0603_6.3V6M  [C_0603]  129.13 132.25 180 top
CA1  10U_0603_6.3V6M  [C_0603]  35.92 16.42 0 top
CA2  0.1U_0201_10V6K  [C_0201]  23.92 16.06 90 top
CA3  10U_0603_6.3V6M  [C_0603]  35.92 17.69 0 top
CA4  0.1U_0201_10V6K  [C_0201]  34.84 16.71 270 top
CA5  10U_0603_6.3V6M  [C_0603]  22.97 14.96 270 top
CA6  0.1U_0201_10V6K  [C_0201]  82.54 133.13 180 top
CA9  0.1U_0201_10V6K  [C_0201]  34.84 20.26 270 top
CA10  100P_0402_50V8J  [C_0402]  24.11 11.77 90 top
CA11  100P_0402_50V8J  [C_0402]  24.11 10.78 270 top
CA12  0.1U_0201_10V6K  [C_0201]  37.64 22.73 90 top
CA13  0.1U_0201_10V6K  [C_0201]  37.64 22.04 270 top
CA15  0.1U_0201_10V6K  [C_0201]  34.84 18.41 90 top
CA16  680P_0402_50V7K  [C_0402]  19.27 10.96 0 top
CA17  680P_0402_50V7K  [C_0402]  21.96 10.96 180 top
CA18  2.2U_0402_6.3V6M  [C_0402]  24.62 14.59 270 top
CA19  2.2U_0402_6.3V6M  [C_0402]  25.89 13.57 270 top
CA20  0.1U_0201_10V6K  [C_0201]  21.48 17.86 0 top
CA21  100P_0402_50V8J  [C_0402]  20.78 17.43 180 top
CA22  4.7U_0402_6.3V6M  [C_0402]  23.17 22.03 270 top
CA23  0.1U_0201_10V6K  [C_0201]  23.92 21.98 270 top
CA24  2.2U_0402_6.3V6M  [C_0402]  27.67 13.57 270 top
CA25  2.2U_0402_6.3V6M  [C_0402]  26.78 13.57 270 top
CA26  0.1U_0201_10V6K  [C_0201]  34.84 14.42 270 top
CA27  2.2U_0402_6.3V6M  [C_0402]  36.16 14 0 top
CA28  0.1U_0201_10V6K  [C_0201]  23.92 17.85 270 top
CA29  10U_0603_6.3V6M  [C_0603]  22.97 17.37 270 top
CA30  0.1U_0201_10V6K  [C_0201]  23.92 18.47 90 top
CA31  4.7U_0402_6.3V6M  [C_0402]  23.17 18.64 180 top
CA32  0.1U_0402_10V7K  [C_0402]  24.9 24.34 90 top
CA33  10U_0603_6.3V6M  [C_0603]  35.92 15.15 0 top
CA34  10U_0603_6.3V6M  [C_0603]  31.35 12.86 0 top
CA35  47P_0201_25V8J  [C_0201]  35.67 25.34 270 bottom
CA36  47P_0201_25V8J  [C_0201]  34.78 25.34 270 bottom
CA37  2.2U_0402_6.3V6M  [C_0402]  27.67 24.6 90 top
CA38  0.1U_0201_10V6K  [C_0201]  29.7 22.55 270 bottom
CA39  47P_0201_25V8J  [C_0201]  31.22 25.34 270 bottom
CA40  47P_0201_25V8J  [C_0201]  29.44 25.34 270 bottom
CA41  1000P_0201_16V7K  [C_0201]  243.07 135.62 90 top
CA42  1000P_0201_16V7K  [C_0201]  243.05 136.86 90 top
CA43  2.2U_0402_6.3V6M  [C_0402]  23.11 20.16 180 top
CA44  0.1U_0201_10V6K  [C_0201]  23.92 20.19 90 top
CA45  1000P_0201_16V7K  [C_0201]  24.35 93.56 90 top
CA46  0.1U_0201_10V6K  [C_0201]  32.11 25.34 270 bottom
CA47  0.1U_0201_10V6K  [C_0201]  30.33 25.34 270 bottom
CA48  0.1U_0201_10V6K  [C_0201]  33.89 25.34 270 bottom
CA49  0.1U_0201_10V6K  [C_0201]  33 25.34 270 bottom
CA50  10U_0603_10V6M  [C_0603]  30.08 10.32 0 top
CA51  10U_0603_10V6M  [C_0603]  30.08 11.59 0 top
CA52  1000P_0201_16V7K  [C_0201]  23.59 92.13 270 top
CA90  2.2U_0402_6.3V6M  [C_0402]  203.56 116.19 270 top
CA99  2.2U_0402_6.3V6M  [C_0402]  207.93 126.53 0 top
CA102  10U_0402_6.3V6M  [C_0402]  197.42 121.7 180 top
CA103  0.1U_0201_10V6K  [C_0201]  200.04 122.36 180 top
CA104  1U_0402_6.3V6K  [C_0402]  199.57 120.81 180 top
CA105  10U_0402_6.3V6M  [C_0402]  197.42 120.81 180 top
CA106  10U_0603_10V6M  [C_0603]  211.63 120.05 0 top
CA107  0.1U_0201_10V6K  [C_0201]  210.43 120.09 270 top
CA108  0.1U_0201_10V6K  [C_0201]  209.91 122.72 0 top
CA109  10U_0603_10V6M  [C_0603]  211.63 121.57 0 top
CA110  0.1U_0201_10V6K  [C_0201]  210.39 121.36 90 top
CA111  680P_0402_50V7K  [C_0402]  201.09 117.24 270 top
CA112  680P_0402_50V7K  [C_0402]  199.57 119.92 180 top
CA113  10U_0402_6.3V6M  [C_0402]  200.08 126.14 180 top
CA114  0.1U_0201_10V6K  [C_0201]  200.17 125.38 180 top
CA115  0.1U_0201_10V6K  [C_0201]  200.17 124.11 180 top
CA116  680P_0402_50V7K  [C_0402]  202.69 117.13 270 top
CA117  680P_0402_50V7K  [C_0402]  199.57 118.78 180 top
CA138  0.1U_0201_10V6K  [C_0201]  200.04 121.55 180 top
CC9  0.1U_0201_10V6K  [C_0201]  124.52 110.27 90 bottom
CC16  0.1U_0201_10V6K  [C_0201]  131.86 93.76 180 top
CC17  0.1U_0201_10V6K  [C_0201]  129.1 101.13 0 bottom
CC18  0.1U_0201_10V6K  [C_0201]  128.76 99.35 0 bottom
CC19  0.1U_0201_10V6K  [C_0201]  129.81 103.79 180 bottom
CC20  22U_0603_6.3V6M  [C_0603]  141.08 95.35 270 top
CC21  22U_0603_6.3V6M  [C_0603]  145.14 95.3 90 top
CC22  22U_0603_6.3V6M  [C_0603]  143.87 95.3 90 top
CC23  0.1U_0201_10V6K  [C_0201]  129.27 109.22 90 bottom
CC24  0.1U_0201_10V6K  [C_0201]  130.14 102.59 180 bottom
CC25  0.1U_0201_10V6K  [C_0201]  137.48 101.89 0 top
CC26  0.1U_0201_10V6K  [C_0201]  130.75 102.58 0 bottom
CC28  0.1U_0201_10V6K  [C_0201]  137.48 103.16 0 top
CC30  0.1U_0201_10V6K  [C_0201]  132.4 108.62 0 bottom
CC31  0.1U_0201_10V6K  [C_0201]  131.68 107.89 270 bottom
CC32  0.1U_0201_10V6K  [C_0201]  130.52 107.55 0 bottom
CC33  0.1U_0201_6.3V6K  [C_0201]  135.87 111.7 270 bottom
CC34  0.1U_0201_10V6K  [C_0201]  137.48 102.52 0 top
CC35  0.1U_0201_10V6K  [C_0201]  131.81 105.79 90 bottom
CC36  0.1U_0201_10V6K  [C_0201]  132.53 105.7 0 bottom
CC37  1U_0402_6.3V6K  [C_0402]  150.65 102.14 0 top
CC38  0.1U_0201_10V6K  [C_0201]  130.14 101.94 180 bottom
CC42  1U_0402_6.3V6K  [C_0402]  137.61 106.04 0 top
CC43  0.1U_0201_10V6K  [C_0201]  132.35 104.43 180 bottom
CC44  0.1U_0201_10V6K  [C_0201]  130.5 106.33 0 bottom
CC48  0.1U_0201_10V6K  [C_0201]  131.93 103.2 270 bottom
CC51  22U_0603_6.3V6M  [C_0603]  143.74 92.81 90 top
CC52  0.1U_0201_10V6K  [C_0201]  130.5 106.97 0 bottom
CC53  0.1U_0201_10V6K  [C_0201]  130.47 105.72 0 bottom
CC54  1U_0402_6.3V6K  [C_0402]  138.21 104.55 0 top
CC59  0.1U_0201_10V6K  [C_0201]  128.48 108.06 180 bottom
CC60  0.1U_0201_10V6K  [C_0201]  126.66 108.11 0 bottom
CC61  22U_0603_6.3V6M  [C_0603]  112.29 110.45 180 top
CC62  0.1U_0201_10V6K  [C_0201]  126.08 101.2 180 bottom
CC63  0.1U_0201_10V6K  [C_0201]  124.82 103.65 270 bottom
CC64  0.1U_0201_10V6K  [C_0201]  126.08 100.08 180 bottom
CC65  0.1U_0201_10V6K  [C_0201]  126.08 101.76 180 bottom
CC66  0.1U_0201_10V6K  [C_0201]  126.08 102.32 180 bottom
CC67  0.1U_0201_10V6K  [C_0201]  126.08 104 180 bottom
CC68  0.1U_0201_10V6K  [C_0201]  126.08 100.64 180 bottom
CC69  0.1U_0201_10V6K  [C_0201]  124.82 101.9 90 bottom
CC70  0.1U_0201_10V6K  [C_0201]  124.25 100.77 0 bottom
CC71  0.1U_0201_10V6K  [C_0201]  124.25 101.33 0 bottom
CC72  0.1U_0201_10V6K  [C_0201]  126.08 102.88 180 bottom
CC73  0.1U_0201_10V6K  [C_0201]  126.08 103.44 180 bottom
CC74  0.1U_0201_10V6K  [C_0201]  127.87 115.51 270 top
CC75  0.1U_0201_10V6K  [C_0201]  120.31 110.9 270 bottom
CC76  0.1U_0201_10V6K  [C_0201]  120.87 110.9 270 bottom
CC77  0.1U_0201_10V6K  [C_0201]  125.71 115.51 270 top
CC78  0.1U_0201_10V6K  [C_0201]  122.83 110.9 270 bottom
CC79  0.1U_0201_10V6K  [C_0201]  126.4 110.87 270 bottom
CC80  0.1U_0201_10V6K  [C_0201]  124.44 115.51 270 top
CC81  0.1U_0201_10V6K  [C_0201]  123.68 115.51 270 top
CC82  0.1U_0201_10V6K  [C_0201]  119.49 115.51 270 top
CC83  0.1U_0201_10V6K  [C_0201]  122.27 110.9 270 bottom
CC84  0.1U_0201_10V6K  [C_0201]  129.14 115.51 270 top
CC85  0.1U_0201_10V6K  [C_0201]  125.56 110.87 270 bottom
CC86  0.1U_0201_10V6K  [C_0201]  119.61 110.92 270 bottom
CC87  0.1U_0201_10V6K  [C_0201]  118.6 115.51 270 top
